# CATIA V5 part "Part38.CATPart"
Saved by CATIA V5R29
Part number: pan head cross recess screw_iso_ISO 7045 - M4 x 16 - Z - 16N
Revision: ANY
Definition: UNKNOWN
Nomenclature: pan head cross recess screw_iso_ISO 7045 - M4 x 16 - Z - 16N
Source: Unknown
Bounding box of the stored display mesh (mm): x 0.079 to 19.1, y -3.991 to 3.991, z -4 to 4
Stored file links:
  C:\Users\Administrator\Desktop\프로젝트\Gripper\Part38.CATPart
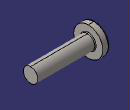
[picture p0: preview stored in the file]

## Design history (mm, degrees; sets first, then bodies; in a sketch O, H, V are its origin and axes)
Body1 "RecessCore" (main body)
  Solid1: solid without history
